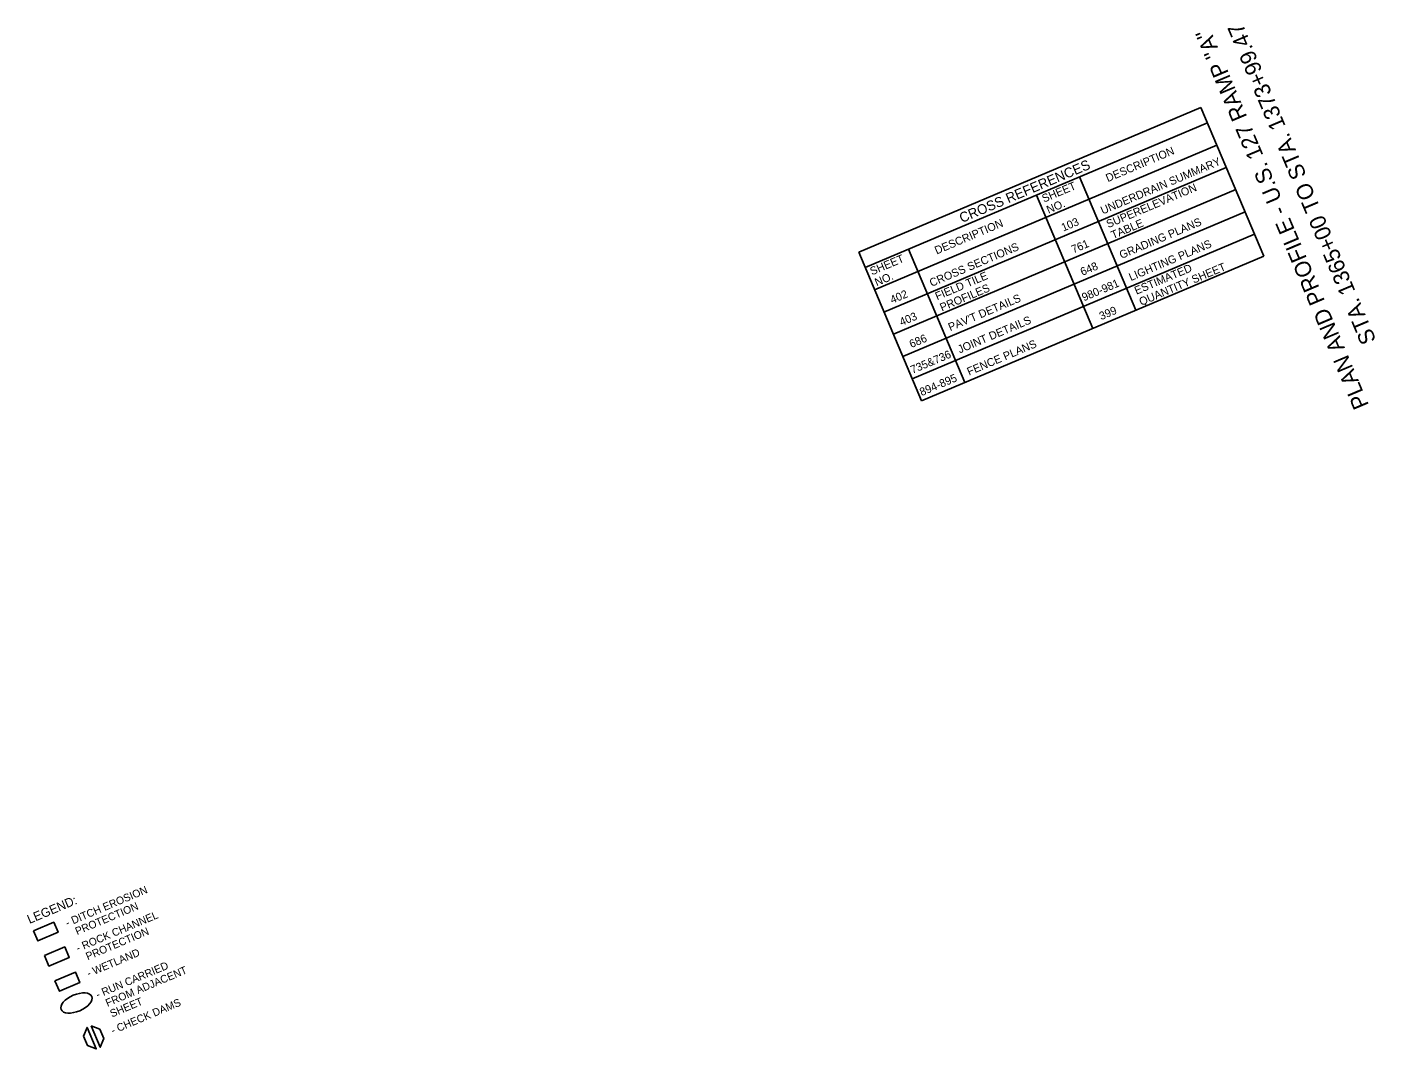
# Model space of a CAD drawing. Extents: x -52514368 to 1397765, y -51297125 to 573700.
# Drawn here: x 1396711 to 1397765, y 572890 to 573689 of the extents above; entities that cross this region are included whole.
import ezdxf

# ---------------------------------------------------------------- set-up
doc = ezdxf.new("R2010")
doc.units = 0
for name, color, linetype in [('Level 1', 7, 'Continuous'), ('Level 15', 7, 'Continuous'), ('Level 38', 7, 'Continuous'), ('Level 40', 7, 'Continuous'), ('Level 55', 7, 'Continuous')]:
    doc.layers.add(name, color=color, linetype=linetype)

msp = doc.modelspace()

# ---------------------------------------------------------------- linework, layer by layer
at = {"layer": 'Level 15'}
msp.add_lwpolyline([(1396732.7, 572943.8), (1396748.7, 572950.5), (1396752.1, 572942.3), (1396736.2, 572935.6)], close=True, dxfattribs=at)
at = {"layer": 'Level 38'}
for p, q in [((1396755, 572900.5), (1396757.8, 572907.3)), ((1396757.8, 572907.3), (1396764.9, 572890.5)), ((1396760.9, 572908.6), (1396768.1, 572891.8)), ((1396767.7, 572905.9), (1396760.9, 572908.6)), ((1396767.7, 572905.9), (1396770.8, 572898.6)), ((1396755, 572900.5), (1396758.1, 572893.2)), ((1396764.9, 572890.5), (1396758.1, 572893.2)), ((1396768.1, 572891.8), (1396770.8, 572898.6))]:
    msp.add_line(p, q, dxfattribs=at)
for points in [[(1396755, 572900.5), (1396757.8, 572907.3), (1396764.9, 572890.5), (1396758.1, 572893.2)], [(1396760.9, 572908.6), (1396767.7, 572905.9), (1396770.8, 572898.6), (1396768.1, 572891.8)]]:
    msp.add_lwpolyline(points, close=True, dxfattribs=at)
at = {"layer": 'Level 40'}
for p, q in [((1397628, 573625.6), (1397360.6, 573512.7)), ((1397628, 573625.6), (1397677, 573509.6)), ((1397633.1, 573613.7), (1397365.7, 573500.7)), ((1397373, 573483.3), (1397640.4, 573596.3)), ((1397380.3, 573466), (1397647.7, 573579)), ((1397533.2, 573571.5), (1397577.2, 573467.4)), ((1397387.7, 573448.6), (1397655.1, 573561.6)), ((1397499.4, 573557.2), (1397543.4, 573453.1)), ((1397395, 573431.3), (1397662.4, 573544.3)), ((1397402.3, 573413.9), (1397669.7, 573526.9)), ((1397399.5, 573515), (1397443.5, 573410.9)), ((1397360.6, 573512.7), (1397409.7, 573396.6)), ((1397409.7, 573396.6), (1397677, 573509.6))]:
    msp.add_line(p, q, dxfattribs=at)
msp.add_ellipse((1396749.5, 572926.4), major_axis=(12, 5.1), ratio=0.5, dxfattribs=at)
at = {"layer": 'Level 55'}
for points in [[(1396715.8, 572982.8), (1396731.7, 572989.5), (1396735.1, 572981.6), (1396719.2, 572974.9)], [(1396724.4, 572963.5), (1396740.3, 572970.2), (1396743.8, 572962), (1396727.9, 572955.3)]]:
    msp.add_lwpolyline(points, close=True, dxfattribs=at)

# ---------------------------------------------------------------- texts
at = {"layer": 'Level 1'}
for s, p in [('PLAN AND PROFILE - U.S. 127 RAMP "A"', (1397759.4, 573393.3)), ('STA. 1365+00 TO STA. 1373+99.47', (1397765.1, 573443.9))]:
    msp.add_text(s, height=12.5, rotation=112.9049, dxfattribs=at).set_placement(p)
at = {"layer": 'Level 40'}
for s, height, p in [('DESCRIPTION', 6.25, (1397555.2, 573567.4)), ('CROSS REFERENCES', 7.692, (1397441.2, 573535.5)), ('UNDERDRAIN SUMMARY', 6.25, (1397551.2, 573542.1)), ('SHEET ', 6.25, (1397505.3, 573551.4)), ('SUPERELEVATION  ', 6.25, (1397555.6, 573531.5)), ('NO.', 6.25, (1397508.9, 573542.7)), ('DESCRIPTION', 6.25, (1397421.5, 573510.9)), (' 103', 6.25, (1397518.3, 573527.9)), ('TABLE           ', 6.25, (1397559.3, 573522.9)), ('GRADING PLANS   ', 6.25, (1397565.8, 573507.4)), ('CROSS SECTIONS  ', 6.25, (1397417.5, 573485.6)), (' 761', 6.25, (1397526.2, 573510.8)), ('LIGHTING PLANS', 6.25, (1397573.2, 573490.1)), ('SHEET ', 6.25, (1397371, 573494.6)), (' 648', 6.25, (1397533.2, 573493.3)), ('QUANTITY SHEET  ', 6.25, (1397581.3, 573470.8)), ('NO.', 6.25, (1397374.7, 573486)), ('FIELD TILE       ', 6.25, (1397421.9, 573475.1)), ('ESTIMATED       ', 6.25, (1397577.6, 573479.5)), (' 402', 6.25, (1397384.6, 573471.5)), ('PROFILES  ', 6.25, (1397425.6, 573466.4)), ('980-981', 6.25, (1397536.5, 573474.3)), ("PAV'T DETAILS   ", 6.25, (1397432.1, 573451)), (' 403', 6.25, (1397391.9, 573454.1)), ('JOINT DETAILS   ', 6.25, (1397439.5, 573433.6)), (' 399', 6.25, (1397547.9, 573458.7)), (' 686', 6.25, (1397399.6, 573436.9)), ('FENCE PLANS     ', 6.25, (1397446.8, 573416.3)), ('735&736', 6.25, (1397402.6, 573417.7)), ('894-895', 6.25, (1397409.8, 573400.3)), ('LEGEND:', 7, (1396712.8, 572988.1)), ('- DITCH EROSION', 6, (1396742.4, 572985.9)), ('  PROTECTION', 6, (1396745.9, 572977.6)), ('- ROCK CHANNEL', 6, (1396750.7, 572966.2)), ('  PROTECTION', 6, (1396754.2, 572958)), ('- WETLAND', 6, (1396759, 572946.5)), ('- RUN CARRIED', 6, (1396766.1, 572929.9)), ('  FROM ADJACENT', 6, (1396769.6, 572921.6)), ('  SHEET', 6, (1396773.1, 572913.3)), ('- CHECK DAMS', 6, (1396777.9, 572901.9))]:
    msp.add_text(s, height=height, rotation=22.9049, dxfattribs=at).set_placement(p)

doc.saveas('drawing.dxf')
